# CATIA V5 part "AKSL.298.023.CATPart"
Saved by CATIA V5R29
Part number: АКСЛ.298.023
Definition: Уголок
Material "Steel": density 7860 kg/m3, Young's modulus 2e+11 Pa, Poisson ratio 0.266, thermal expansion 1.17e-05 1/K
Bounding box of the stored display mesh (mm): x -149 to 149, y -51 to 52, z -51 to 52
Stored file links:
  Z:\ООО Аксель\Соединения бруса\Соединения бруса\Соединения из листа\АКСЛ.298.020 (Дуо)\AKSL.298.023.CATPart
  Z:\ООО Аксель\Соединения бруса\Соединения бруса\Соединения из листа\АКСЛ.298.020 (Дуо)\AKSL.298.020.CATProduct
  Z:\#Catalog_GosNIIAS\Holes&Pockets\Part\Соединение шип-паз\Ship-Paz.CATPart
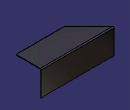
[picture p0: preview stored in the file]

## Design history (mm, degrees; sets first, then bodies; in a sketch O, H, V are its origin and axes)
External parameters (linked from other documents)
  `External.S металла` = 2 mm
  `External.R гиба` = 1.9 mm
  `External.K factor` = 0.49
SheetMetalParameters1: Thickness 2 {= `External.S металла`}, BendRadius 1.9 {= `External.R гиба`}, KFactor 0.49 {= `External.K factor`}, ReliefRadialLength 1, ReliefAxialLength 2, MinimumBendRadius 0
Set1
  DatumSurface1: linked copy from another document
  Plane1: linked copy from another document
  Plane2: linked copy from another document
  DatumCurve1: linked copy from another document
  DatumCurve2: linked copy from another document
  Plane3: linked copy from another document
Body1 (main body)
  ThickSurface1: BotOffset 0, Surface DatumSurface1, TopOffset 2 {= `External.S металла`}
  Split1: SplitPlane Plane1
  Split2: SplitPlane Plane3
  Recognize1: Recognize_BendTable SheetMetalParameters1, Recognize_ReferenceFace face of ThickSurface1, Recognize_BendDefaultRadius 1.9 {= `External.R гиба`}, KFacteur 0.49 {= SheetMetalParameters1.KFactor}
  d_Bend1: Bend_BendTable SheetMetalParameters1, Bend_Thickness 2 {= `External.S металла`}, Bend_KFactor 0.49 {= SheetMetalParameters1.KFactor}, Bend_FirstSupport face of Recognize1, Bend_SecondSupport face of Recognize1, Bend_KFactorRadius 1.9 {= d_Bend1.CylindricalBendSurf_Radius}, Bend_Deduction -3.2761 {= (d_Bend1.CylindricalBendSurf_Radius+SheetMetalParameters1.Thickness*d_Bend1.Bend_KFactor)*(PI-abs(d_Bend1.BendSurf_OpenAngle))-2*(d_Bend1.CylindricalBendSurf_Radius+SheetMetalParameters1.Thickness)*tan(min((PI-abs(d_Bend1.BendSurf_OpenAngle)),(PI/2))/2)}
  Sketch1 on face of Recognize1, origin (0, 52, 0), H (-1, 0, 0), V (0, 0, 1)
    construction line L1 (151, -109) -> (151, 121)
    reference intersected line E1 through (151, 0) direction (0, -1) from Plane2
    construction line L2 (149, 106) -> (149, -111)
    line L3 (151, 56) -> (149, 56)
    line L4 (149, 56) -> (149, -75)
    line L5 (149, -75) -> (151, -75)
    line L6 (151, -75) -> (151, 56)
    distance L1 L2 = 2 {= `External.S металла`}
    vertical: L1 V, L2 V, L4 V, L6 V
    coincidence: E1 L1, L6 L1, L4 L2
    horizontal: L3 H, L5 H
  CutOut1: Direction Sketch1, EndLimit through (limit type 3), Orientation true, Profile Sketch1, StartLimit through (limit type 2), Thickness1 2, Thickness2 2
  CutOut2: Direction Sketch4, EndLimit through (limit type 2), Orientation true, Profile Sketch4, StartLimit through (limit type 2)
  CutOut3: Direction Sketch3.C2, EndLimit through (limit type 3), Orientation true, Profile Sketch3.C2, StartLimit through (limit type 2), Thickness1 2, Thickness2 2
  CutOut4: Direction Sketch3.C1, EndLimit through (limit type 3), Orientation true, Profile Sketch3.C1, StartLimit through (limit type 2), Thickness1 2, Thickness2 2
  Wall1: Thickness 2 {= `External.S металла`}, Profile Sketch2, ListTangentTo face of Recognize1, OffsetValue 0
  Sketch2 on face of Recognize1, origin (0, 0, 52), H (1, 0, 0), V (0, 1, 0)
    reference projected line E1 (-49, -50) -> (149, -50) from edge [face of Recognize1 | face of Recognize1]
    point P1 (-49, -50)
    point P2 (149, -50)
    point P3 (-39, -50)
    line L1 (-39, -50) -> (139, -50)
    line L2 (139, -50) -> (139, -51)
    line L3 (139, -51) -> (-39, -51)
    line L4 (-39, -51) -> (-39, -50)
    distance L2 P2 = 10
    distance L4 P1 = 10
    distance L1 L3 = 1
    coincidence: P3 E1
    horizontal: L1 H, L3 H
    vertical: L2 V, L4 V
  Sketch3 on face of Recognize1, origin (0, 52, 0), H (-1, 0, 0), V (0, 0, 1)
    reference projected line E1 (149, -52) -> (149, 48.1) from edge [face of CutOut1 | face of Recognize1]
    projected line E2 (-149, -52) -> (-149, 48.1) from edge [face of Recognize1 | face of Recognize1]
    point P3 (-149, -52)
    point P4 (-149, 48.1)
    reference projected line E4 (-139.5, -52) -> (-139.5, -50) from edge [face of CutOut2 | face of Recognize1]
    point P7 (-139.5, -52)
    construction line L1 (139.5, -52) -> (149, -52)
    line L2 (139.5, -52) -> (149, -52)
    line L3 (149, -52) -> (149, -51)
    line L4 (149, -51) -> (139.5, -51)
    line L5 (139.5, -51) -> (139.5, -52)
    point P10 (149, -51)
    point P12 (-139.5, -51)
    line L6 (-139.5, -51) -> (-149, -51)
    line L7 (-149, -52) -> (-149, -51)
    line L8 (-139.5, -51) -> (-139.5, -52)
    curve C1
    curve C2
    line L9 (-149, -52) -> (-139.5, -52)
    distance L2 L4 = 1
    horizontal: L1 H, L2 H, L4 H, L6 H, L9 H
    vertical: L3 V, L5 V, L7 V, L8 V
    coincidence: P10 E1, P12 L8, P12 L6, P4 L7, P7 L9, P3 L9
    midpoint: P12 E4
  Sketch4 on DatumCurve1, origin (-139, 51, -50), H (1, 0, 0), V (0, 0, 1)
    reference projected line E1 (0, -2) -> (0, 0) from DatumCurve2
    reference projected line E2 (0, 0) -> (278, 0) from DatumCurve1
    construction line L1 (0, -1) -> (139, -1)
    point P5 (0, -1)
    point P6 (139, -1)
    axis line L2 (139, 0) -> (139, 7.3468)
    point P7 (139, 0)
    line L3 (278.5, -2) -> (278.5, 0)
    line L4 (278.5, 0) -> (-0.5, 0)
    line L5 (-0.5, 0) -> (-0.5, -2)
    line L6 (-0.5, -2) -> (278.5, -2)
    distance L5 E1 = 0.5
    distance E2 L4 = 0
    midpoint: P5 E1, P7 E2
    coincidence: L2 P6
    equidistance: L3 L5 P6, L4 L6 P6
    parallelism: L1 E2, L2 E1, L6 L4, L3 L5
